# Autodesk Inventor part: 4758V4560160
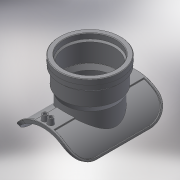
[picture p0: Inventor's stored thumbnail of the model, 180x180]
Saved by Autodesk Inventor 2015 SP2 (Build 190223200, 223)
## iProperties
Created: 2017-08
Part Number: 4758V4560160
Material: Generic
Description: PLASSON WASTEWATER SADDLE 355-560X160 PVC/PP ADAPTOR INLET
Document SubType Name: Modeling
Designer: Кирилл
Density: 1 g/cm^3
Appearance: Default
Author: Кирилл
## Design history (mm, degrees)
derived "4758V4.ipt"
feature "Solid1::4758V4.ipt"
feature "Solid2::4758V4.ipt"
feature "Solid3::4758V4.ipt"
tag "TaggingFeature1"
body "Solid1"
other parameters: "d1" = 263, "d2" = 582.4, "d4" = 0, "d5" = 78.9, "d6" = 6.4, "d7" = 20 deg, "d8" = 10 deg, "d10" = 0, "d11" = 364, "d38" = 2.8, "d40" = 306, "d41" = 15, "d42" = 130.5, "d43" = 17.6, "d44" = 8.8, "d46" = 5 deg, "d47" = 4, "d49" = 4, "d51" = 14, "d52" = 0, "d53" = 3, "d54" = 0, "d57" = 0.5, "d59" = 16, "d60" = 5.6, "d61" = 40 deg, "d62" = 152, "d63" = 156.8, "d64" = 144, "d65" = 155 deg, "d66" = 125, "d68" = 188.1, "d69" = 45 deg, "d70" = 175, "d72" = 7.5, "d75" = 0, "d77" = 0, "d78" = 1.6, "d81" = 37.5, "B_" = 263, "H_" = 125, "d71" = 7.5
